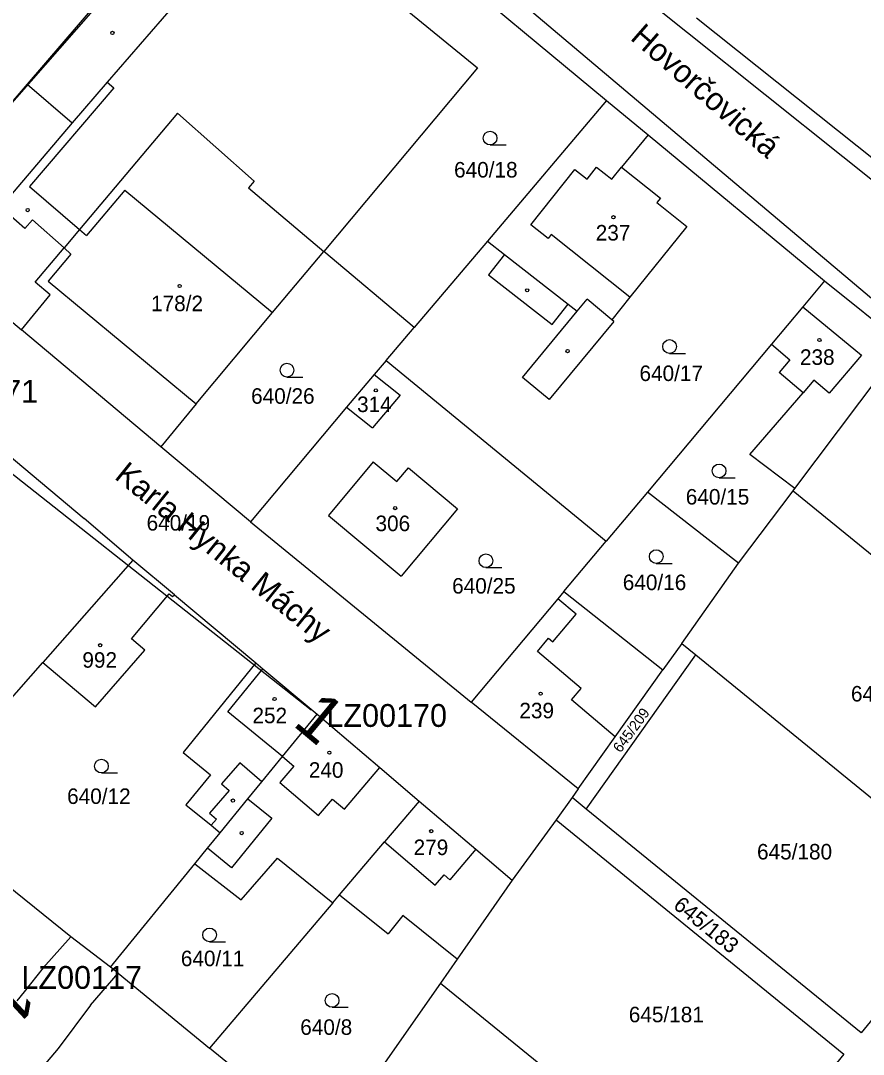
# Model space of a CAD drawing. Extents: x -738131 to -734179, y -1033447 to -1030078.
# Drawn here: x -735833.8 to -735741.5, y -1032576 to -1032462.8 of the extents above; entities that cross this region are included whole.
import ezdxf

# ---------------------------------------------------------------- set-up
doc = ezdxf.new("R2010")
doc.units = 0
for name, color, linetype in [('ftf_2010', 7, 'Continuous'), ('ftf_3010', 7, 'Continuous'), ('ftf_3010_ftf_3010_gtda_3015_gtda_3015_1', 7, 'Continuous'), ('ftf_nu', 7, 'Continuous'), ('Vrstva 1', 7, 'Continuous'), ('Vrstva 2', 7, 'Continuous'), ('Vrstva 3', 7, 'Continuous'), ('Vrstva 4', 7, 'Continuous'), ('Vrstva 5', 7, 'Continuous')]:
    doc.layers.add(name, color=color, linetype=linetype)

msp = doc.modelspace()

# ---------------------------------------------------------------- linework, layer by layer
at = {"layer": 'ftf_2010'}
for points in [[(-735777.75, -1032450.49), (-735735.23, -1032484.5)], [(-735821.15, -1032456.3), (-735847.57, -1032486.43)], [(-735801.94, -1032538.34), (-735846.61, -1032503.08)]]:
    msp.add_lwpolyline(points, dxfattribs=at)
at = {"layer": 'Vrstva 1'}
for points in [[(-735811.27, -1032433.53), (-735736.15, -1032496.99)], [(-735819.66, -1032454.16), (-735833.05, -1032469.78)], [(-735789.52, -1032455.02), (-735769.63, -1032471.55)], [(-735792.66, -1032460.72), (-735783.75, -1032467.99)], [(-735759.77, -1032462.52), (-735717.94, -1032495.86)], [(-735783.75, -1032467.99), (-735800.57, -1032488.09)], [(-735833.05, -1032469.78), (-735846.73, -1032485.72)], [(-735769.63, -1032471.55), (-735782.65, -1032486.98)], [(-735769.63, -1032471.55), (-735765.07, -1032475.33)], [(-735816.58, -1032472.95), (-735827.31, -1032485.69)], [(-735816.58, -1032472.95), (-735808.19, -1032480.4)], [(-735765.07, -1032475.33), (-735767.99, -1032478.86)], [(-735765.07, -1032475.33), (-735745.74, -1032491.33)], [(-735767.99, -1032478.86), (-735763.72, -1032482.27)], [(-735808.19, -1032480.4), (-735808.83, -1032481.13)], [(-735808.83, -1032481.13), (-735800.57, -1032488.09)], [(-735763.72, -1032482.27), (-735764.1, -1032482.75)], [(-735764.1, -1032482.75), (-735760.83, -1032485.36)], [(-735827.31, -1032485.69), (-735829.01, -1032487.71)], [(-735760.83, -1032485.36), (-735767.05, -1032493.09)], [(-735832.18, -1032491.48), (-735829.01, -1032487.71)], [(-735782.65, -1032486.98), (-735790.67, -1032496.41)], [(-735782.65, -1032486.98), (-735780.8, -1032488.42)], [(-735806.2, -1032494.77), (-735800.57, -1032488.09)], [(-735790.67, -1032496.41), (-735800.57, -1032488.09)], [(-735780.8, -1032488.42), (-735782.54, -1032490.65)], [(-735782.54, -1032490.65), (-735775.56, -1032496.1)], [(-735745.74, -1032491.33), (-735748.11, -1032494.15)], [(-735745.74, -1032491.33), (-735737.09, -1032498.24)], [(-735839.19, -1032492.06), (-735833.66, -1032496.7)], [(-735830.51, -1032492.86), (-735832.18, -1032491.48)], [(-735833.66, -1032496.7), (-735830.51, -1032492.86)], [(-735767.05, -1032493.09), (-735769.05, -1032495.57)], [(-735814.55, -1032504.79), (-735806.2, -1032494.77)], [(-735778.82, -1032501.89), (-735772.83, -1032494.64)], [(-735775.56, -1032496.1), (-735773.82, -1032493.87)], [(-735773.82, -1032493.87), (-735772.83, -1032494.64)], [(-735748.11, -1032494.15), (-735751.56, -1032498.27)], [(-735768.81, -1032495.77), (-735775.88, -1032504.32)], [(-735768.81, -1032495.77), (-735769.05, -1032495.57)], [(-735818.42, -1032509.51), (-735833.66, -1032496.7)], [(-735793.74, -1032500.03), (-735790.67, -1032496.41)], [(-735751.56, -1032498.27), (-735765.15, -1032514.47)], [(-735751.56, -1032498.27), (-735749.55, -1032499.97)], [(-735748.99, -1032514.05), (-735737.09, -1032498.24)], [(-735793.74, -1032500.03), (-735795.06, -1032501.58)], [(-735793.74, -1032500.03), (-735769.65, -1032519.83)], [(-735749.55, -1032499.97), (-735750.73, -1032501.37)], [(-735795.06, -1032501.58), (-735798.09, -1032505.16)], [(-735795.06, -1032501.58), (-735792.22, -1032503.83)], [(-735748.1, -1032503.6), (-735750.73, -1032501.37)], [(-735775.88, -1032504.32), (-735778.82, -1032501.89)], [(-735792.22, -1032503.83), (-735795.25, -1032507.41)], [(-735753.92, -1032510.33), (-735748.1, -1032503.6)], [(-735842.79, -1032503.95), (-735826.79, -1032517.35)], [(-735814.55, -1032504.79), (-735818.42, -1032509.51)], [(-735798.09, -1032505.16), (-735808.58, -1032517.71)], [(-735798.09, -1032505.16), (-735795.25, -1032507.41)], [(-735808.58, -1032517.71), (-735818.42, -1032509.51)], [(-735748.99, -1032514.05), (-735753.92, -1032510.33)], [(-735795.15, -1032511.15), (-735800.04, -1032517.02)], [(-735795.15, -1032511.15), (-735792.56, -1032513.31)], [(-735792.56, -1032513.31), (-735791.31, -1032511.81)], [(-735791.31, -1032511.81), (-735785.95, -1032516.3)], [(-735749.18, -1032514.31), (-735748.99, -1032514.05)], [(-735765.15, -1032514.47), (-735769.65, -1032519.83)], [(-735755.17, -1032522.23), (-735765.15, -1032514.47)], [(-735755.17, -1032522.23), (-735749.18, -1032514.31)], [(-735749.18, -1032514.31), (-735715.63, -1032541.65)], [(-735785.95, -1032516.3), (-735792.11, -1032523.65)], [(-735821.46, -1032521.9), (-735826.79, -1032517.35)], [(-735800.04, -1032517.02), (-735792.11, -1032523.65)], [(-735808.58, -1032517.71), (-735784.44, -1032537.45)], [(-735774.28, -1032525.35), (-735769.65, -1032519.83)], [(-735821.46, -1032521.9), (-735831.33, -1032533.11)], [(-735816.93, -1032525.69), (-735821.46, -1032521.9)], [(-735761.39, -1032531.02), (-735755.17, -1032522.23)], [(-735774.28, -1032525.35), (-735774.95, -1032526.15)], [(-735774.28, -1032525.35), (-735763.44, -1032533.91)], [(-735821.61, -1032530.51), (-735817.51, -1032525.58)], [(-735817.51, -1032525.58), (-735817.13, -1032525.9)], [(-735817.13, -1032525.9), (-735816.93, -1032525.69)], [(-735816.93, -1032525.69), (-735808, -1032533.16)], [(-735774.95, -1032526.15), (-735784.44, -1032537.45)], [(-735820.17, -1032531.77), (-735821.61, -1032530.51)], [(-735761.39, -1032531.02), (-735763.44, -1032533.91)], [(-735761.39, -1032531.02), (-735759.84, -1032532.28)], [(-735825.55, -1032537.98), (-735820.17, -1032531.77)], [(-735845.54, -1032549.25), (-735831.33, -1032533.11)], [(-735831.33, -1032533.11), (-735825.55, -1032537.98)], [(-735808, -1032533.16), (-735815.97, -1032542.98)], [(-735808, -1032533.16), (-735807.23, -1032533.8)], [(-735771.83, -1032549.18), (-735759.84, -1032532.28)], [(-735759.84, -1032532.28), (-735728.69, -1032557.67)], [(-735807.23, -1032533.8), (-735801.29, -1032538.77)], [(-735768.67, -1032541.25), (-735763.44, -1032533.91)], [(-735772.72, -1032546.96), (-735784.44, -1032537.45)], [(-735805.08, -1032543.41), (-735801.29, -1032538.77)], [(-735801.29, -1032538.77), (-735794.43, -1032544.63)], [(-735772.72, -1032546.96), (-735768.67, -1032541.25)], [(-735815.97, -1032542.98), (-735812.98, -1032545.41)], [(-735807.36, -1032546.2), (-735805.08, -1032543.41)], [(-735812.98, -1032545.41), (-735815.66, -1032548.71)], [(-735794.43, -1032544.63), (-735790.14, -1032548.29)], [(-735808.88, -1032548.05), (-735807.36, -1032546.2)], [(-735773.38, -1032547.91), (-735775.14, -1032550.34)], [(-735772.72, -1032546.96), (-735773.38, -1032547.91)], [(-735771.83, -1032549.18), (-735773.38, -1032547.91)], [(-735815.66, -1032548.71), (-735812.91, -1032550.94)], [(-735811.93, -1032551.79), (-735808.88, -1032548.05)], [(-735790.14, -1032548.29), (-735793.94, -1032552.77)], [(-735790.14, -1032548.29), (-735783.92, -1032553.58)], [(-735828.25, -1032563.15), (-735845.54, -1032549.25)], [(-735741.74, -1032573.69), (-735771.83, -1032549.18)], [(-735812.91, -1032550.94), (-735811.93, -1032551.79)], [(-735775.14, -1032550.34), (-735779.94, -1032556.96)], [(-735775.14, -1032550.34), (-735743.64, -1032576.01)], [(-735813.3, -1032553.47), (-735811.93, -1032551.79)], [(-735814.69, -1032555.17), (-735813.3, -1032553.47)], [(-735798.84, -1032558.55), (-735793.94, -1032552.77)], [(-735783.92, -1032553.58), (-735779.94, -1032556.96)], [(-735809.62, -1032559.11), (-735805.65, -1032554.55)], [(-735805.65, -1032554.55), (-735799.59, -1032559.45)], [(-735823.92, -1032566.47), (-735814.69, -1032555.17)], [(-735814.69, -1032555.17), (-735809.62, -1032559.11)], [(-735779.94, -1032556.96), (-735785.97, -1032565.61)], [(-735728.69, -1032557.67), (-735741.74, -1032573.69)], [(-735799.59, -1032559.45), (-735798.84, -1032558.55)], [(-735798.84, -1032558.55), (-735793.53, -1032562.84)], [(-735799.59, -1032559.45), (-735813.08, -1032575.37)], [(-735791.92, -1032560.82), (-735793.53, -1032562.84)], [(-735785.97, -1032565.61), (-735791.92, -1032560.82)], [(-735828.25, -1032563.15), (-735831.3, -1032566.57)], [(-735823.92, -1032566.47), (-735828.25, -1032563.15)], [(-735785.97, -1032565.61), (-735787.81, -1032568.23)], [(-735831.3, -1032566.57), (-735833.37, -1032569.18)], [(-735826.12, -1032570.64), (-735823.08, -1032567.16)], [(-735823.08, -1032567.16), (-735823.92, -1032566.47)], [(-735823.08, -1032567.16), (-735813.08, -1032575.37)], [(-735787.81, -1032568.23), (-735800.15, -1032585.92)], [(-735787.81, -1032568.23), (-735757.44, -1032592.96)], [(-735833.37, -1032569.18), (-735834.19, -1032570.19)], [(-735826.12, -1032570.64), (-735829.66, -1032575.39)], [(-735829.66, -1032575.39), (-735834.43, -1032581.05)], [(-735802.16, -1032584.28), (-735813.08, -1032575.37)], [(-735743.64, -1032576.01), (-735757.44, -1032592.96)]]:
    msp.add_lwpolyline(points, dxfattribs=at)
at = {"layer": 'Vrstva 3'}
for p, q in [((-735782.36, -1032476.43), (-735780.61, -1032476.43)), ((-735762.71, -1032499.26), (-735760.96, -1032499.26)), ((-735804.6, -1032501.85), (-735802.85, -1032501.85)), ((-735757.3, -1032512.88), (-735755.55, -1032512.88)), ((-735782.82, -1032522.72), (-735781.07, -1032522.72)), ((-735764.18, -1032522.27), (-735762.43, -1032522.27)), ((-735824.92, -1032545.21), (-735823.17, -1032545.21)), ((-735813.08, -1032563.7), (-735811.33, -1032563.7)), ((-735799.67, -1032570.88), (-735797.92, -1032570.88))]:
    msp.add_line(p, q, dxfattribs=at)
for centre in [(-735782.36, -1032475.68), (-735762.71, -1032498.51), (-735804.6, -1032501.1), (-735757.3, -1032512.13), (-735764.18, -1032521.52), (-735782.82, -1032521.97), (-735824.92, -1032544.46), (-735813.08, -1032562.95), (-735799.67, -1032570.13)]:
    msp.add_circle(centre, 0.75, dxfattribs=at)
at = {"layer": 'Vrstva 4'}
for points in [[(-735814.65, -1032458.41), (-735824.28, -1032469.56)], [(-735833.05, -1032469.78), (-735828.13, -1032474.03)], [(-735824.28, -1032469.56), (-735828.13, -1032474.03)], [(-735824.28, -1032469.56), (-735823.56, -1032470.18)], [(-735823.56, -1032470.18), (-735832.78, -1032480.98)], [(-735828.13, -1032474.03), (-735841.69, -1032489.95)], [(-735771.74, -1032480.17), (-735770.71, -1032478.88)], [(-735770.71, -1032478.88), (-735769.05, -1032480.19)], [(-735769.05, -1032480.19), (-735767.99, -1032478.86)], [(-735777.9, -1032485.2), (-735773.07, -1032479.11)], [(-735773.07, -1032479.11), (-735771.74, -1032480.17)], [(-735832.78, -1032480.98), (-735827.31, -1032485.69)], [(-735822.36, -1032481.39), (-735826.54, -1032486.36)], [(-735822.36, -1032481.39), (-735806.2, -1032494.77)], [(-735833.3, -1032485.58), (-735835.11, -1032483.97)], [(-735832.47, -1032484.64), (-735833.3, -1032485.58)], [(-735832.47, -1032484.64), (-735829.01, -1032487.71)], [(-735827.31, -1032485.69), (-735826.54, -1032486.36)], [(-735776.01, -1032486.69), (-735777.9, -1032485.2)], [(-735775.67, -1032486.26), (-735776.01, -1032486.69)], [(-735767.05, -1032493.09), (-735775.67, -1032486.26)], [(-735829.01, -1032487.71), (-735828.25, -1032488.38)], [(-735828.25, -1032488.38), (-735830.76, -1032491.36)], [(-735780.8, -1032488.42), (-735773.82, -1032493.87)], [(-735830.76, -1032491.36), (-735814.55, -1032504.79)], [(-735772.83, -1032494.64), (-735771.75, -1032493.34)], [(-735769.05, -1032495.57), (-735771.75, -1032493.34)], [(-735748.11, -1032494.15), (-735741.72, -1032499.44)], [(-735741.72, -1032499.44), (-735745.26, -1032503.62)], [(-735746.92, -1032502.21), (-735748.1, -1032503.6)], [(-735745.26, -1032503.62), (-735746.92, -1032502.21)], [(-735772.95, -1032527.84), (-735774.95, -1032526.15)], [(-735775.51, -1032530.86), (-735772.95, -1032527.84)], [(-735777.18, -1032531.9), (-735775.97, -1032530.47)], [(-735775.97, -1032530.47), (-735775.51, -1032530.86)], [(-735772.39, -1032535.96), (-735777.18, -1032531.9)], [(-735811.08, -1032538.52), (-735807.23, -1032533.8)], [(-735773.44, -1032537.2), (-735772.39, -1032535.96)], [(-735768.67, -1032541.25), (-735773.44, -1032537.2)], [(-735805.08, -1032543.41), (-735811.08, -1032538.52)], [(-735805.08, -1032543.41), (-735803.84, -1032544.47)], [(-735809.78, -1032544.11), (-735811.77, -1032546.41)], [(-735807.36, -1032546.2), (-735809.78, -1032544.11)], [(-735803.84, -1032544.47), (-735805.37, -1032546.25)], [(-735798.32, -1032549.19), (-735794.43, -1032544.63)], [(-735811.77, -1032546.41), (-735810.94, -1032547.13)], [(-735805.37, -1032546.25), (-735801.14, -1032549.87)], [(-735810.94, -1032547.13), (-735813.08, -1032549.61)], [(-735808.88, -1032548.05), (-735806.26, -1032550.18)], [(-735801.14, -1032549.87), (-735799.61, -1032548.08)], [(-735799.61, -1032548.08), (-735798.32, -1032549.19)], [(-735813.08, -1032549.61), (-735812.32, -1032550.26)], [(-735812.32, -1032550.26), (-735812.91, -1032550.94)], [(-735806.26, -1032550.18), (-735810.68, -1032555.6)], [(-735810.68, -1032555.6), (-735813.3, -1032553.47)], [(-735793.94, -1032552.77), (-735788.38, -1032557.51)], [(-735783.92, -1032553.58), (-735786.76, -1032556.91)], [(-735788.38, -1032557.51), (-735787.4, -1032556.36)], [(-735787.4, -1032556.36), (-735786.76, -1032556.91)]]:
    msp.add_lwpolyline(points, dxfattribs=at)
at = {"layer": 'Vrstva 5'}
for centre in [(-735823.71, -1032464.16), (-735832.99, -1032483.57), (-735768.86, -1032484.35), (-735816.35, -1032491.88), (-735778.31, -1032492.35), (-735746.31, -1032497.8), (-735773.88, -1032499.01), (-735794.87, -1032503.31), (-735792.76, -1032516.21), (-735825.05, -1032531.23), (-735776.83, -1032536.53), (-735805.96, -1032537.12), (-735799.96, -1032543), (-735810.52, -1032548.24), (-735809.56, -1032551.8), (-735788.81, -1032551.59)]:
    msp.add_circle(centre, 0.175, dxfattribs=at)

# ---------------------------------------------------------------- texts
at = {"layer": 'ftf_3010'}
for rotation, p in [(320.1812, (-735804.1, -1032539.92)), (222.7228, (-735835.14, -1032566.73))]:
    msp.add_text('1', height=5.2, rotation=rotation, dxfattribs=at).set_placement(p)
at = {"layer": 'ftf_3010_ftf_3010_gtda_3015_gtda_3015_1'}
for s, p in [('LZ00171', (-735845.04, -1032504.67)), ('LZ00170', (-735800.28, -1032540.17))]:
    msp.add_text(s, height=2.5, dxfattribs=at).set_placement(p)
msp.add_text('LZ00117', height=2.5, rotation=0, dxfattribs=at).set_placement((-735833.67, -1032568.86))
at = {"layer": 'ftf_nu'}
for s, rotation, p in [('Hovorčovická', 318.9274, (-735767.13, -1032464.83)), ('Karla Hynka Máchy', 321.073, (-735823.6, -1032512.91))]:
    msp.add_text(s, height=2.5, rotation=rotation, dxfattribs=at).set_placement(p)
at = {"layer": 'Vrstva 2'}
for s, p in [('640/18', (-735786.31, -1032480)), ('237', (-735770.8, -1032486.9)), ('178/2', (-735819.48, -1032494.64)), ('238', (-735748.44, -1032500.52)), ('640/17', (-735766.01, -1032502.29)), ('640/26', (-735808.53, -1032504.78)), ('314', (-735796.93, -1032505.69)), ('640/15', (-735760.94, -1032515.82)), ('640/19', (-735819.97, -1032518.67)), ('306', (-735794.91, -1032518.73)), ('640/25', (-735786.52, -1032525.57)), ('640/16', (-735767.84, -1032525.19)), ('992', (-735827, -1032533.69)), ('645/179', (-735742.86, -1032537.39)), ('239', (-735779.16, -1032539.23)), ('252', (-735808.38, -1032539.77)), ('240', (-735802.21, -1032545.74)), ('640/12', (-735828.67, -1032548.61)), ('279', (-735790.74, -1032554.21)), ('645/180', (-735753.14, -1032554.69)), ('640/11', (-735816.22, -1032566.38)), ('645/181', (-735767.18, -1032572.52)), ('640/8', (-735803.15, -1032573.9))]:
    msp.add_text(s, height=1.7, dxfattribs=at).set_placement(p)
for s, height, rotation, p in [('645/209', 1.14, 53.6864, (-735768.09, -1032543.08)), ('645/183', 1.7, 321.0441, (-735762.42, -1032559.92))]:
    msp.add_text(s, height=height, rotation=rotation, dxfattribs=at).set_placement(p)

doc.saveas('drawing.dxf')
